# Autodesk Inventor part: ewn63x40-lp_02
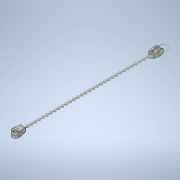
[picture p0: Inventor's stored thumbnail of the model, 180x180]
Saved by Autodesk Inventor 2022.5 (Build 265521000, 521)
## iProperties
Created: 2021-08
Part Number: ewn63x40-lp_02
Material: 一般
Document SubType Name: Modeling
Designer: ImaoCorp
Density: 1 g/cm^3
Appearance: 既定
Author: ImaoCorp
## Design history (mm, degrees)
feature "ewn63x40-lp_02"
node "ソリッド1"
